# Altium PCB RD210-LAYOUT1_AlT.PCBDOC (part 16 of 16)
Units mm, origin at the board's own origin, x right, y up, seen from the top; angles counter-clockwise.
Board outline 330 x 300 mm, 6 copper layers (TOP, Mid-Layer 1, Mid-Layer 2, Mid-Layer 3, Mid-Layer 4, BOTTOM), stack 1.422 mm thick; 981 components, 463 nets, 2326 pads, 12534 vias.
Unrouted connection lines stored in the file: 6.
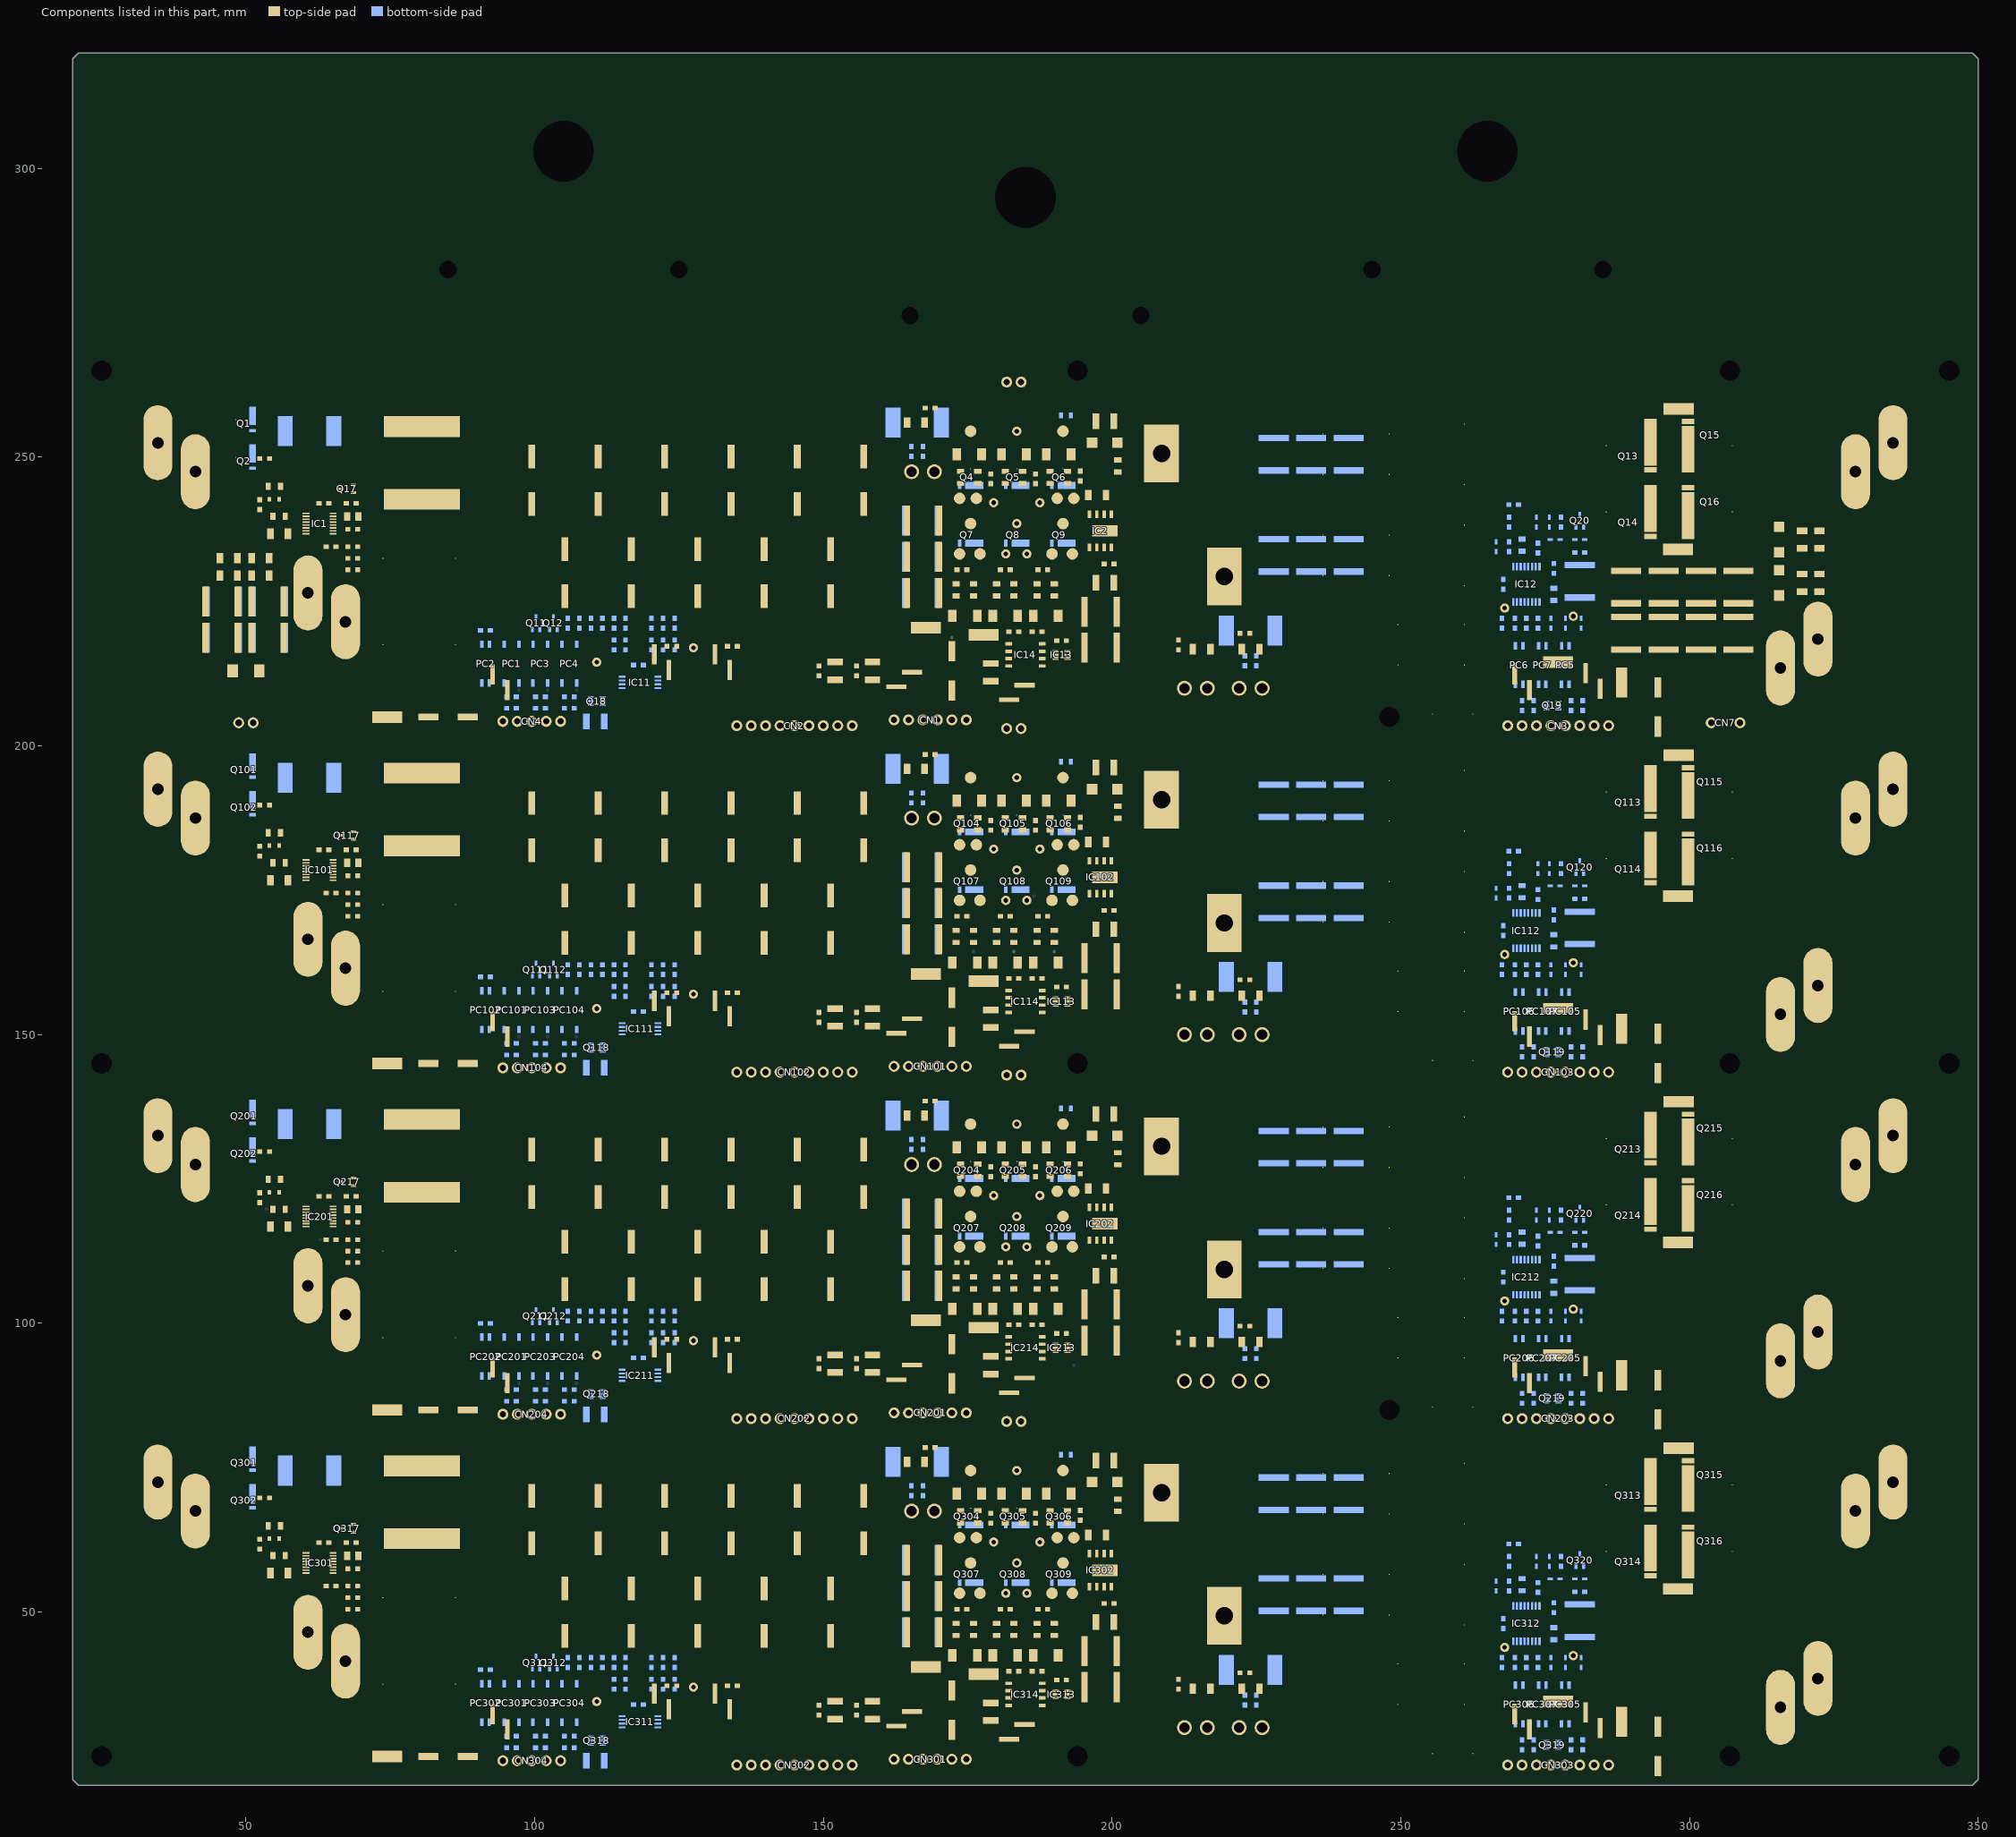
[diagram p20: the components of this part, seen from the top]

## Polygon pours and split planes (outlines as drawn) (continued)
no net on Bottom Solder "BOTTOMSOLDER1619" (solid, pour order 0): 189.245,190.25 189.245,191.55 189.945,191.55 189.945,190.25
no net on Bottom Solder "BOTTOMSOLDER1620" (solid, pour order 0): 190.515,190.25 190.515,191.55 191.215,191.55 191.215,190.25
no net on Bottom Solder "BOTTOMSOLDER1621" (solid, pour order 0): 191.785,190.25 191.785,191.55 192.485,191.55 192.485,190.25
no net on Bottom Solder "BOTTOMSOLDER1622" (solid, pour order 0): 193.055,190.25 193.055,191.55 193.755,191.55 193.755,190.25
no net on Bottom Solder "BOTTOMSOLDER1623" (solid, pour order 0): 21 vertices, not listed, extent 188.7,186.65 194.3,189.95
no net on Bottom Solder "BOTTOMSOLDER1624" (solid, pour order 0): 177.055,174.45 177.055,175.75 177.755,175.75 177.755,174.45
no net on Bottom Solder "BOTTOMSOLDER1625" (solid, pour order 0): 174.515,174.45 174.515,175.75 175.215,175.75 175.215,174.45
no net on Bottom Solder "BOTTOMSOLDER1626" (solid, pour order 0): 173.245,180.25 173.245,181.55 173.945,181.55 173.945,180.25
no net on Bottom Solder "BOTTOMSOLDER1627" (solid, pour order 0): 174.515,180.25 174.515,181.55 175.215,181.55 175.215,180.25
no net on Bottom Solder "BOTTOMSOLDER1628" (solid, pour order 0): 175.785,180.25 175.785,181.55 176.485,181.55 176.485,180.25
no net on Bottom Solder "BOTTOMSOLDER1629" (solid, pour order 0): 177.055,180.25 177.055,181.55 177.755,181.55 177.755,180.25
no net on Bottom Solder "BOTTOMSOLDER1630" (solid, pour order 0): 21 vertices, not listed, extent 172.7,176.65 178.3,179.95
no net on Bottom Solder "BOTTOMSOLDER1631" (solid, pour order 0): 185.055,174.45 185.055,175.75 185.755,175.75 185.755,174.45
no net on Bottom Solder "BOTTOMSOLDER1632" (solid, pour order 0): 182.515,174.45 182.515,175.75 183.215,175.75 183.215,174.45
no net on Bottom Solder "BOTTOMSOLDER1633" (solid, pour order 0): 181.245,180.25 181.245,181.55 181.945,181.55 181.945,180.25
no net on Bottom Solder "BOTTOMSOLDER1634" (solid, pour order 0): 182.515,180.25 182.515,181.55 183.215,181.55 183.215,180.25
no net on Bottom Solder "BOTTOMSOLDER1635" (solid, pour order 0): 183.785,180.25 183.785,181.55 184.485,181.55 184.485,180.25
no net on Bottom Solder "BOTTOMSOLDER1636" (solid, pour order 0): 185.055,180.25 185.055,181.55 185.755,181.55 185.755,180.25
no net on Bottom Solder "BOTTOMSOLDER1637" (solid, pour order 0): 21 vertices, not listed, extent 180.7,176.65 186.3,179.95
no net on Bottom Solder "BOTTOMSOLDER1638" (solid, pour order 0): 193.055,174.45 193.055,175.75 193.755,175.75 193.755,174.45
no net on Bottom Solder "BOTTOMSOLDER1639" (solid, pour order 0): 190.515,174.45 190.515,175.75 191.215,175.75 191.215,174.45
no net on Bottom Solder "BOTTOMSOLDER1640" (solid, pour order 0): 189.245,180.25 189.245,181.55 189.945,181.55 189.945,180.25
no net on Bottom Solder "BOTTOMSOLDER1641" (solid, pour order 0): 190.515,180.25 190.515,181.55 191.215,181.55 191.215,180.25
no net on Bottom Solder "BOTTOMSOLDER1642" (solid, pour order 0): 191.785,180.25 191.785,181.55 192.485,181.55 192.485,180.25
no net on Bottom Solder "BOTTOMSOLDER1643" (solid, pour order 0): 193.055,180.25 193.055,181.55 193.755,181.55 193.755,180.25
no net on Bottom Solder "BOTTOMSOLDER1644" (solid, pour order 0): 21 vertices, not listed, extent 188.7,176.65 194.3,179.95
no net on Bottom Solder "BOTTOMSOLDER1645" (solid, pour order 0): 259.25,303 ccw(c265,303) 270.75,303 ccw(c265,303)
no net on Bottom Solder "BOTTOMSOLDER1646" (solid, pour order 0): 179.25,295 ccw(c185,295) 190.75,295 ccw(c185,295)
no net on Bottom Solder "BOTTOMSOLDER1647" (solid, pour order 0): 99.25,303 ccw(c105,303) 110.75,303 ccw(c105,303)
no net on Bottom Solder "BOTTOMSOLDER1648" (solid, pour order 0): 289.5,284.5 289.5,280.5 280.5,280.5 280.5,284.5
no net on Bottom Solder "BOTTOMSOLDER1649" (solid, pour order 0): 240.5,280.5 240.5,284.5 249.5,284.5 249.5,280.5
no net on Bottom Solder "BOTTOMSOLDER1650" (solid, pour order 0): 200.5,272.5 200.5,276.5 209.5,276.5 209.5,272.5
no net on Bottom Solder "BOTTOMSOLDER1651" (solid, pour order 0): 160.5,272.5 160.5,276.5 169.5,276.5 169.5,272.5
no net on Bottom Solder "BOTTOMSOLDER1652" (solid, pour order 0): 120.5,280.5 120.5,284.5 129.5,284.5 129.5,280.5
no net on Bottom Solder "BOTTOMSOLDER1653" (solid, pour order 0): 80.5,280.5 80.5,284.5 89.5,284.5 89.5,280.5

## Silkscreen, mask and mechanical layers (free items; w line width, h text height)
Top Overlay:
  drawing of 30636 lines, arcs and shapes, not listed
Bottom Overlay:
  drawing of 18949 lines, arcs and shapes, not listed
Mechanical 3:
  lines w0.001: 19.95,11 ccw(c20,11) 20.05,11 20.05,19 ccw(c20,19) 19.95,19 19.95,11 ; 19.95,21 ccw(c20,21) 20.05,21 20.05,319 ccw(c20,319) 19.95,319 19.95,21 ; 19.95,321 ccw(c20,321) 19.965,320.965 20.965,319.965 ccw(c21,320) 21.035,320.035 20.05,321.021 20.05,329 ccw(c20,329) 19.95,329 19.95,321 ; 19.965,10.965 cw(c20,11) 20.035,11.035 21.035,10.035 cw(c21,10) 20.965,9.965 19.965,10.965 ; 19.965,19.035 ccw(c20,19) 20.035,18.965 21.035,19.965 ccw(c21,20) 20.965,20.035 19.965,19.035 ; 19.965,20.965 cw(c20,21) 20.035,21.035 21.035,20.035 cw(c21,20) 20.965,19.965 19.965,20.965 ; 19.965,319.035 ccw(c20,319) 20.035,318.965 21.035,319.965 ccw(c21,320) 20.965,320.035 19.965,319.035 ; 19.965,329.035 ccw(c20,329) 20.035,328.965 21.035,329.965 ccw(c21,330) 20.965,330.035 19.965,329.035 ; 21,9.95 cw(c21,10) 21,10.05 349,10.05 cw(c349,10) 349,9.95 21,9.95 ; 21,19.95 cw(c21,20) 21,20.05 349,20.05 cw(c349,20) 349,19.95 21,19.95 ; 21,319.95 cw(c21,320) 21,320.05 349,320.05 cw(c349,320) 349,319.95 21,319.95 ; 21,329.95 cw(c21,330) 21,330.05 349,330.05 cw(c349,330) 349,329.95 21,329.95 ; 348.965,10.035 ccw(c349,10) 349.035,9.965 350.035,10.965 ccw(c350,11) 349.965,11.035 348.965,10.035 ; 348.965,19.965 cw(c349,20) 349.035,20.035 350.035,19.035 cw(c350,19) 349.965,18.965 348.965,19.965 ; 348.965,20.035 ccw(c349,20) 349.035,19.965 350.035,20.965 ccw(c350,21) 349.965,21.035 348.965,20.035 ; 348.965,319.965 cw(c349,320) 349.035,320.035 350.035,319.035 cw(c350,319) 349.965,318.965 348.965,319.965 ; 348.965,320.035 ccw(c349,320) 349.035,319.965 350.035,320.965 ccw(c350,321) 349.965,321.035 348.965,320.035 ; 348.965,329.965 cw(c349,330) 349.035,330.035 350.035,329.035 cw(c350,329) 349.965,328.965 348.965,329.965 ; 349.95,11 ccw(c350,11) 350.05,11 350.05,19 ccw(c350,19) 349.95,19 349.95,11 ; 349.95,21 ccw(c350,21) 350.05,21 350.05,319 ccw(c350,319) 349.95,319 349.95,21 ; 349.95,321 ccw(c350,321) 350.05,321 350.05,329 ccw(c350,329) 349.95,329 349.95,321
